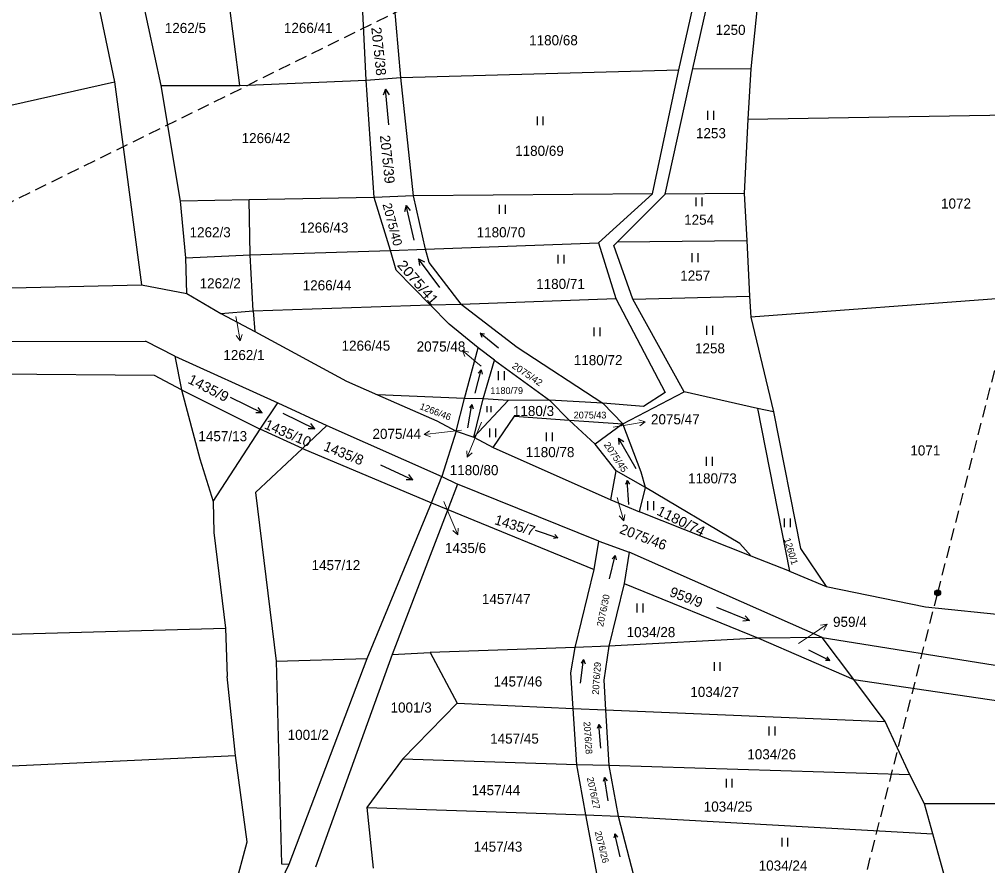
# Model space of a CAD drawing. Extents: x -820420 to -815896, y -1105820 to -1103643.
# Drawn here: x -818424.2 to -818260.8, y -1104579.4 to -1104436.5 of the extents above; entities that cross this region are included whole.
import ezdxf
from ezdxf.enums import TextEntityAlignment as Align

# ---------------------------------------------------------------- set-up
doc = ezdxf.new("R2010")
doc.units = 0
doc.header["$LTSCALE"] = 0.68
doc.linetypes.add('MEDIUM_DASHED', pattern=[4.5, 3, -1.5])
for name, color, linetype, lineweight in [('1', 7, 'Continuous', 25), ('3', 7, 'Continuous', 25), ('6', 7, 'Continuous', 25), ('7', 7, 'Continuous', 13)]:
    doc.layers.add(name, color=color, linetype=linetype, lineweight=lineweight)
doc.layers.add('2', color=7, linetype='Continuous')

msp = doc.modelspace()

# ---------------------------------------------------------------- linework, layer by layer
at = {"layer": '1'}
for p, q in [((-818419, -1104394.95), (-818408.15, -1104447.11)), ((-818400.28, -1104447.7), (-818404.63, -1104427.35)), ((-818386.97, -1104447.71), (-818389.54, -1104427.58)), ((-818359.79, -1104446.38), (-818361.33, -1104428.52)), ((-818312.89, -1104445.04), (-818309.55, -1104430.24)), ((-818310.49, -1104444.84), (-818307.33, -1104430.54)), ((-818299.29, -1104430.76), (-818300.71, -1104444.9)), ((-818359.79, -1104446.38), (-818312.89, -1104445.04)), ((-818317.32, -1104466.01), (-818312.89, -1104445.04)), ((-818315.17, -1104466.05), (-818310.49, -1104444.84)), ((-818310.49, -1104444.84), (-818300.71, -1104444.9)), ((-818300.71, -1104444.9), (-818301.21, -1104453.37)), ((-818451.46, -1104456.83), (-818408.15, -1104447.11)), ((-818408.15, -1104447.11), (-818403.58, -1104481.37)), ((-818386.97, -1104447.71), (-818365.63, -1104446.8)), ((-818365.63, -1104446.8), (-818359.79, -1104446.38)), ((-818364.31, -1104466.64), (-818365.63, -1104446.8)), ((-818357.69, -1104466.34), (-818359.79, -1104446.38)), ((-818396.98, -1104467.21), (-818400.28, -1104447.7)), ((-818400.28, -1104447.7), (-818386.97, -1104447.71)), ((-818301.21, -1104453.37), (-818226.13, -1104452.14)), ((-818301.21, -1104453.37), (-818301.84, -1104465.94)), ((-818385.42, -1104466.98), (-818396.98, -1104467.21)), ((-818364.31, -1104466.64), (-818385.42, -1104466.98)), ((-818385.26, -1104476.32), (-818385.42, -1104466.98)), ((-818357.69, -1104466.34), (-818364.31, -1104466.64)), ((-818361.57, -1104475.54), (-818364.31, -1104466.64)), ((-818317.32, -1104466.01), (-818357.69, -1104466.34)), ((-818355.64, -1104475.33), (-818357.69, -1104466.34)), ((-818326.41, -1104474.27), (-818317.32, -1104466.01)), ((-818323.25, -1104474.12), (-818315.17, -1104466.05)), ((-818301.84, -1104465.94), (-818315.17, -1104466.05)), ((-818301.84, -1104465.94), (-818301.42, -1104473.9)), ((-818396.12, -1104476.78), (-818396.98, -1104467.21)), ((-818355.64, -1104475.33), (-818326.41, -1104474.27)), ((-818326.41, -1104474.27), (-818323.5, -1104483.66)), ((-818323.83, -1104474.71), (-818323.25, -1104474.12)), ((-818320.65, -1104483.76), (-818323.83, -1104474.71)), ((-818323.25, -1104474.12), (-818301.42, -1104473.9)), ((-818301.42, -1104473.9), (-818300.93, -1104483.27)), ((-818396.12, -1104476.78), (-818385.26, -1104476.32)), ((-818395.9, -1104482.8), (-818396.12, -1104476.78)), ((-818385.26, -1104476.32), (-818361.57, -1104475.54)), ((-818384.71, -1104485.74), (-818385.26, -1104476.32)), ((-818361.57, -1104475.54), (-818355.64, -1104475.33)), ((-818360.6, -1104478.86), (-818361.57, -1104475.54)), ((-818355.04, -1104477.57), (-818355.64, -1104475.33)), ((-818349.6, -1104484.6), (-818355.04, -1104477.57)), ((-818354.87, -1104484.72), (-818360.6, -1104478.86)), ((-818513.64, -1104483.89), (-818403.58, -1104481.37)), ((-818403.58, -1104481.37), (-818395.9, -1104482.8)), ((-818395.9, -1104482.8), (-818390.18, -1104486.22)), ((-818320.65, -1104483.76), (-818300.93, -1104483.27)), ((-818300.93, -1104483.27), (-818300.75, -1104486.83)), ((-818250.48, -1104483.05), (-818300.75, -1104486.83)), ((-818384.71, -1104485.74), (-818354.87, -1104484.72)), ((-818354.87, -1104484.72), (-818349.6, -1104484.6)), ((-818351.62, -1104488.01), (-818354.87, -1104484.72)), ((-818349.6, -1104484.6), (-818323.5, -1104483.66)), ((-818349.6, -1104484.6), (-818340.14, -1104491.86)), ((-818323.5, -1104483.66), (-818315.18, -1104499.54)), ((-818311.99, -1104499.41), (-818320.65, -1104483.76)), ((-818390.18, -1104486.22), (-818384.71, -1104485.74)), ((-818390.18, -1104486.22), (-818384.47, -1104489.23)), ((-818384.71, -1104485.74), (-818384.47, -1104489.23)), ((-818346.76, -1104491.98), (-818351.62, -1104488.01)), ((-818300.75, -1104486.83), (-818296.92, -1104502.82)), ((-818384.47, -1104489.23), (-818368.98, -1104497.61)), ((-818428.81, -1104490.91), (-818402.92, -1104490.85)), ((-818397.95, -1104493.39), (-818402.92, -1104490.85)), ((-818349.08, -1104500.56), (-818346.76, -1104491.98)), ((-818343.99, -1104494.06), (-818346.76, -1104491.98)), ((-818340.14, -1104491.86), (-818325.7, -1104501.31)), ((-818397.95, -1104493.39), (-818396.82, -1104499.07)), ((-818397.95, -1104493.39), (-818380.57, -1104501.26)), ((-818345.91, -1104500.62), (-818343.99, -1104494.06)), ((-818343.99, -1104494.06), (-818334.7, -1104500.84)), ((-818401.41, -1104496.65), (-818518.56, -1104495.77)), ((-818396.82, -1104499.07), (-818401.41, -1104496.65)), ((-818368.98, -1104497.61), (-818363.75, -1104499.92)), ((-818396.82, -1104499.07), (-818383.56, -1104505.7)), ((-818396.82, -1104499.07), (-818393.74, -1104510.75)), ((-818322.31, -1104504.84), (-818311.99, -1104499.41)), ((-818315.18, -1104499.54), (-818318.86, -1104501.87)), ((-818299.59, -1104502.21), (-818311.99, -1104499.41)), ((-818383.56, -1104505.7), (-818380.57, -1104501.26)), ((-818380.57, -1104501.26), (-818372.32, -1104505.09)), ((-818363.75, -1104499.92), (-818353.72, -1104504.34)), ((-818350.45, -1104506.05), (-818349.08, -1104500.56)), ((-818347.5, -1104507.08), (-818345.91, -1104500.62)), ((-818341.67, -1104500.87), (-818347.5, -1104507.08)), ((-818341.67, -1104500.87), (-818345.91, -1104500.62)), ((-818334.7, -1104500.84), (-818341.67, -1104500.87)), ((-818325.7, -1104501.31), (-818334.7, -1104500.84)), ((-818334.7, -1104500.84), (-818331.4, -1104504.2)), ((-818322.31, -1104504.84), (-818325.7, -1104501.31)), ((-818318.86, -1104501.87), (-818325.7, -1104501.31)), ((-818299.59, -1104502.21), (-818294.22, -1104529.71)), ((-818296.92, -1104502.82), (-818299.59, -1104502.21)), ((-818296.92, -1104502.82), (-818292.32, -1104525.87)), ((-818353.72, -1104504.34), (-818350.45, -1104506.05)), ((-818344.21, -1104508.8), (-818340.61, -1104503.54)), ((-818340.61, -1104503.54), (-818331.4, -1104504.2)), ((-818331.4, -1104504.2), (-818327, -1104508.25)), ((-818331.4, -1104504.2), (-818322.31, -1104504.84)), ((-818391.49, -1104517.94), (-818383.56, -1104505.7)), ((-818376.38, -1104509.01), (-818383.56, -1104505.7)), ((-818372.32, -1104505.09), (-818376.38, -1104509.01)), ((-818372.32, -1104505.09), (-818352.91, -1104513.7)), ((-818350.45, -1104506.05), (-818352.91, -1104513.7)), ((-818350.45, -1104506.05), (-818347.5, -1104507.08)), ((-818322.31, -1104504.84), (-818327, -1104508.25)), ((-818319.22, -1104512.98), (-818322.31, -1104504.84)), ((-818347.5, -1104507.08), (-818344.21, -1104508.8)), ((-818376.38, -1104509.01), (-818384.31, -1104516.44)), ((-818376.38, -1104509.01), (-818354.64, -1104518.15)), ((-818344.21, -1104508.8), (-818324.37, -1104517.66)), ((-818323.48, -1104512.75), (-818327, -1104508.25)), ((-818393.74, -1104510.75), (-818391.49, -1104517.94)), ((-818324.37, -1104517.66), (-818323.48, -1104512.75)), ((-818318.48, -1104515.55), (-818323.48, -1104512.75)), ((-818354.64, -1104518.15), (-818352.91, -1104513.7)), ((-818352.91, -1104513.7), (-818350.22, -1104514.98)), ((-818318.48, -1104515.55), (-818319.22, -1104512.98)), ((-818350.22, -1104514.98), (-818351.89, -1104519.31)), ((-818326.39, -1104524.63), (-818350.22, -1104514.98)), ((-818319.51, -1104519.7), (-818318.48, -1104515.55)), ((-818302.6, -1104525), (-818318.48, -1104515.55)), ((-818384.31, -1104516.44), (-818380.84, -1104544.89)), ((-818324.37, -1104517.66), (-818319.51, -1104519.7)), ((-818391.49, -1104517.94), (-818391.39, -1104523.17)), ((-818365.48, -1104544.43), (-818354.64, -1104518.15)), ((-818351.89, -1104519.31), (-818361.28, -1104543.79)), ((-818354.64, -1104518.15), (-818351.89, -1104519.31)), ((-818351.89, -1104519.31), (-818327.16, -1104529.42)), ((-818300.68, -1104527.15), (-818319.51, -1104519.7)), ((-818391.39, -1104523.17), (-818389.39, -1104539.29)), ((-818327.16, -1104529.42), (-818326.39, -1104524.63)), ((-818326.39, -1104524.63), (-818321.26, -1104526.51)), ((-818302.6, -1104525), (-818300.68, -1104527.15)), ((-818321.26, -1104526.51), (-818322.13, -1104531.79)), ((-818288.7, -1104540.87), (-818321.26, -1104526.51)), ((-818294.22, -1104529.71), (-818300.68, -1104527.15)), ((-818292.32, -1104525.87), (-818288, -1104532.29)), ((-818330.35, -1104542.58), (-818327.16, -1104529.42)), ((-818294.22, -1104529.71), (-818288, -1104532.29)), ((-818322.13, -1104531.79), (-818324.7, -1104542.33)), ((-818322.13, -1104531.79), (-818299.45, -1104541)), ((-818288, -1104532.29), (-818271.24, -1104535.73)), ((-818271.24, -1104535.73), (-818252.18, -1104537.64)), ((-818465.14, -1104541.42), (-818389.39, -1104539.29)), ((-818389.39, -1104539.29), (-818389.11, -1104547.47)), ((-818299.45, -1104541), (-818324.7, -1104542.33)), ((-818288.7, -1104540.87), (-818299.45, -1104541)), ((-818299.45, -1104541), (-818283.33, -1104547.98)), ((-818288.7, -1104540.87), (-818248.29, -1104547.36)), ((-818283.33, -1104547.98), (-818288.7, -1104540.87)), ((-818361.28, -1104543.79), (-818374.22, -1104579.64)), ((-818361.28, -1104543.79), (-818354.85, -1104543.45)), ((-818330.35, -1104542.58), (-818354.85, -1104543.45)), ((-818354.85, -1104543.45), (-818350.28, -1104551.98)), ((-818331.12, -1104546.83), (-818330.35, -1104542.58)), ((-818324.7, -1104542.33), (-818330.35, -1104542.58)), ((-818324.7, -1104542.33), (-818325.56, -1104548.11)), ((-818380.84, -1104544.89), (-818365.48, -1104544.43)), ((-818380.84, -1104544.89), (-818379.96, -1104579.08)), ((-818378.66, -1104579.17), (-818365.48, -1104544.43)), ((-818330.72, -1104552.87), (-818331.12, -1104546.83)), ((-818387.71, -1104560.84), (-818389.11, -1104547.47)), ((-818325.56, -1104548.11), (-818325.26, -1104553.1)), ((-818283.33, -1104547.98), (-818211.91, -1104558.58)), ((-818278.05, -1104555.07), (-818283.33, -1104547.98)), ((-818350.28, -1104551.98), (-818359.51, -1104561.45)), ((-818350.28, -1104551.98), (-818330.72, -1104552.87)), ((-818330.72, -1104552.87), (-818325.26, -1104553.1)), ((-818330.09, -1104562.4), (-818330.72, -1104552.87)), ((-818325.26, -1104553.1), (-818278.05, -1104555.07)), ((-818325.26, -1104553.1), (-818324.7, -1104562.48)), ((-818273.9, -1104564.1), (-818278.05, -1104555.07)), ((-818489.62, -1104565.43), (-818387.71, -1104560.84)), ((-818385.75, -1104575.41), (-818387.71, -1104560.84)), ((-818359.51, -1104561.45), (-818365.54, -1104569.6)), ((-818330.09, -1104562.4), (-818359.51, -1104561.45)), ((-818328.55, -1104570.82), (-818330.09, -1104562.4)), ((-818324.7, -1104562.48), (-818330.09, -1104562.4)), ((-818273.9, -1104564.1), (-818324.7, -1104562.48)), ((-818324.7, -1104562.48), (-818323.1, -1104571.04)), ((-818271.4, -1104568.99), (-818273.9, -1104564.1)), ((-818365.54, -1104569.6), (-818364.46, -1104579.82)), ((-818365.54, -1104569.6), (-818328.55, -1104570.82)), ((-818177.63, -1104569.05), (-818271.4, -1104568.99)), ((-818269.99, -1104574.05), (-818271.4, -1104568.99)), ((-818326.67, -1104581), (-818328.55, -1104570.82)), ((-818328.55, -1104570.82), (-818323.1, -1104571.04)), ((-818323.1, -1104571.04), (-818320.52, -1104581)), ((-818323.1, -1104571.04), (-818269.99, -1104574.05)), ((-818267.52, -1104583.01), (-818269.99, -1104574.05)), ((-818391.09, -1104595.37), (-818385.75, -1104575.41)), ((-818385.92, -1104594.27), (-818378.66, -1104579.17)), ((-818379.96, -1104579.08), (-818378.66, -1104579.17))]:
    msp.add_line(p, q, dxfattribs=at)
for points in [[(-818365.63, -1104446.8), (-818366.53, -1104428.31), (-818367.08, -1104418.7)], [(-818345.91, -1104500.62), (-818349.08, -1104500.56), (-818363.75, -1104499.92)]]:
    msp.add_lwpolyline(points, dxfattribs=at)
at = {"layer": '3'}
for p, q in [((-818362.374, -1104448.344), (-818361.79, -1104449.273)), ((-818307.971, -1104453.48), (-818307.971, -1104451.98)), ((-818306.97, -1104453.48), (-818306.97, -1104451.98)), ((-818336.761, -1104454.43), (-818336.761, -1104452.93)), ((-818335.76, -1104454.43), (-818335.76, -1104452.93)), ((-818309.961, -1104468.09), (-818309.961, -1104466.59)), ((-818308.96, -1104468.09), (-818308.96, -1104466.59)), ((-818358.91, -1104467.978), (-818358.202, -1104468.818)), ((-818343.121, -1104469.36), (-818343.121, -1104467.86)), ((-818342.12, -1104469.36), (-818342.12, -1104467.86)), ((-818333.221, -1104477.78), (-818333.221, -1104476.28)), ((-818332.22, -1104477.78), (-818332.22, -1104476.28)), ((-818310.621, -1104477.52), (-818310.621, -1104476.02)), ((-818309.62, -1104477.52), (-818309.62, -1104476.02)), ((-818356.819, -1104476.995), (-818355.83, -1104477.474)), ((-818346.417, -1104489.503), (-818345.697, -1104489.654)), ((-818327.161, -1104490.05), (-818327.161, -1104488.55)), ((-818326.16, -1104490.05), (-818326.16, -1104488.55)), ((-818308.131, -1104489.8), (-818308.131, -1104488.3)), ((-818307.13, -1104489.8), (-818307.13, -1104488.3)), ((-818346.265, -1104495.73), (-818346.098, -1104496.446)), ((-818343.331, -1104497.44), (-818343.331, -1104495.94)), ((-818342.33, -1104497.44), (-818342.33, -1104495.94)), ((-818383.202, -1104502.97), (-818384.3, -1104502.993)), ((-818347.793, -1104501.56), (-818347.576, -1104502.263)), ((-818345.232, -1104502.87), (-818345.232, -1104501.865)), ((-818344.562, -1104502.87), (-818344.562, -1104501.865)), ((-818374.342, -1104505.66), (-818375.44, -1104505.683)), ((-818344.761, -1104507.09), (-818344.761, -1104505.59)), ((-818343.76, -1104507.09), (-818343.76, -1104505.59)), ((-818335.221, -1104507.76), (-818335.221, -1104506.26)), ((-818334.22, -1104507.76), (-818334.22, -1104506.26)), ((-818323.061, -1104507.233), (-818322.138, -1104507.828)), ((-818308.221, -1104511.92), (-818308.221, -1104510.42)), ((-818307.22, -1104511.92), (-818307.22, -1104510.42)), ((-818357.779, -1104514.263), (-818358.877, -1104514.304)), ((-818321.605, -1104514.403), (-818321.224, -1104515.033)), ((-818318.121, -1104519.39), (-818318.121, -1104517.89)), ((-818317.12, -1104519.39), (-818317.12, -1104517.89)), ((-818295.051, -1104522.28), (-818295.051, -1104520.78)), ((-818294.05, -1104522.28), (-818294.05, -1104520.78)), ((-818333.299, -1104524.04), (-818334.026, -1104524.157)), ((-818323.625, -1104527.06), (-818323.458, -1104527.776)), ((-818319.901, -1104536.67), (-818319.901, -1104535.17)), ((-818318.9, -1104536.67), (-818318.9, -1104535.17)), ((-818300.976, -1104538.038), (-818302.07, -1104538.137)), ((-818328.968, -1104544.634), (-818328.714, -1104545.325)), ((-818306.881, -1104546.54), (-818306.881, -1104545.04)), ((-818305.88, -1104546.54), (-818305.88, -1104545.04)), ((-818287.396, -1104544.751), (-818288.131, -1104544.766)), ((-818326.38, -1104555.576), (-818325.989, -1104556.199)), ((-818297.611, -1104557.41), (-818297.611, -1104555.91)), ((-818296.61, -1104557.41), (-818296.61, -1104555.91)), ((-818325.411, -1104564.523), (-818324.976, -1104565.117)), ((-818304.851, -1104566.24), (-818304.851, -1104564.74)), ((-818303.85, -1104566.24), (-818303.85, -1104564.74)), ((-818323.679, -1104574.019), (-818323.205, -1104574.581)), ((-818295.461, -1104576.2), (-818295.461, -1104574.7)), ((-818294.46, -1104576.2), (-818294.46, -1104574.7))]:
    msp.add_line(p, q, dxfattribs=at)
for points in [[(-818361.851, -1104454.321), (-818362.374, -1104448.344), (-818362.789, -1104449.361)], [(-818357.561, -1104473.824), (-818358.91, -1104467.978), (-818359.179, -1104469.043)], [(-818353.208, -1104481.787), (-818356.819, -1104476.995), (-818356.631, -1104478.077)], [(-818343.293, -1104492.033), (-818346.417, -1104489.503), (-818346.12, -1104490.176)], [(-818347.238, -1104499.631), (-818346.265, -1104495.73), (-818346.75, -1104496.284)], [(-818388.595, -1104500.34), (-818383.202, -1104502.97), (-818383.86, -1104502.091)], [(-818348.491, -1104505.519), (-818347.793, -1104501.56), (-818348.238, -1104502.147)], [(-818379.735, -1104503.03), (-818374.342, -1104505.66), (-818375, -1104504.781)], [(-818320.061, -1104512.429), (-818323.061, -1104507.233), (-818323.007, -1104508.33)], [(-818363.217, -1104511.727), (-818357.779, -1104514.263), (-818358.453, -1104513.395)], [(-818321.325, -1104518.413), (-818321.605, -1104514.403), (-818321.895, -1104515.08)], [(-818337.122, -1104522.798), (-818333.299, -1104524.04), (-818333.818, -1104523.518)], [(-818324.598, -1104530.961), (-818323.625, -1104527.06), (-818324.11, -1104527.614)], [(-818306.539, -1104535.791), (-818300.976, -1104538.038), (-818301.694, -1104537.207)], [(-818291.009, -1104542.989), (-818287.396, -1104544.751), (-818287.837, -1104544.162)], [(-818329.458, -1104548.624), (-818328.968, -1104544.634), (-818329.381, -1104545.243)], [(-818326.03, -1104559.58), (-818326.38, -1104555.576), (-818326.658, -1104556.257)], [(-818324.782, -1104568.493), (-818325.411, -1104564.523), (-818325.64, -1104565.222)], [(-818322.775, -1104577.936), (-818323.679, -1104574.019), (-818323.859, -1104574.733)]]:
    msp.add_lwpolyline(points, dxfattribs=at)
at = {"layer": '6', "linetype": 'MEDIUM_DASHED'}
for p, q in [((-818329.14, -1104419.82), (-818425.57, -1104467.38)), ((-818292.37, -1104624.54), (-818269.18, -1104533.35))]:
    msp.add_line(p, q, dxfattribs=at)
msp.add_lwpolyline([(-818269.18, -1104533.35), (-818248.07, -1104451.05), (-818232.5, -1104368.04)], dxfattribs=at)
at = {"layer": '6'}
for radius in [0.5, 0.4, 0.3, 0.2, 0.1]:
    msp.add_circle((-818269.1834, -1104533.3499), radius, dxfattribs=at)
at = {"layer": '7'}
for p, q in [((-818386.909, -1104490.815), (-818386.59, -1104489.742)), ((-818349.419, -1104492.441), (-818348.974, -1104493.468)), ((-818318.576, -1104504.501), (-818319.643, -1104504.163)), ((-818355.869, -1104506.626), (-818354.814, -1104507.001)), ((-818348.584, -1104510.472), (-818347.745, -1104509.732)), ((-818322.183, -1104521.205), (-818321.978, -1104520.104)), ((-818350.177, -1104523.572), (-818350.108, -1104522.455)), ((-818287.852, -1104538.662), (-818288.962, -1104538.807))]:
    msp.add_line(p, q, dxfattribs=at)
for points in [[(-818387.64, -1104486.69), (-818387.43, -1104487.86), (-818386.909, -1104490.815), (-818387.576, -1104489.916)], [(-818346.26, -1104495.1), (-818347.12, -1104494.37), (-818349.419, -1104492.441), (-818348.33, -1104492.701)], [(-818346.2, -1104504.55), (-818347.46, -1104507.69), (-818348.584, -1104510.472), (-818348.673, -1104509.356)], [(-818323.95, -1104505.37), (-818321.54, -1104504.97), (-818318.576, -1104504.501), (-818319.487, -1104505.152)], [(-818349.57, -1104505.87), (-818352.89, -1104506.26), (-818355.869, -1104506.626), (-818354.936, -1104506.007)], [(-818323.31, -1104517.26), (-818323.01, -1104518.32), (-818322.183, -1104521.205), (-818322.94, -1104520.38)], [(-818352.55, -1104517.95), (-818351.35, -1104520.81), (-818350.177, -1104523.572), (-818351.03, -1104522.846)], [(-818292.65, -1104541.89), (-818290.34, -1104540.34), (-818287.852, -1104538.662), (-818288.402, -1104539.637)]]:
    msp.add_lwpolyline(points, dxfattribs=at)

# ---------------------------------------------------------------- texts
at = {"layer": '2'}
for s, height, p in [('1262/5', 1.7, (-818396.17, -1104438.845)), ('1266/41', 1.7, (-818375.429, -1104438.835)), ('1250', 1.7, (-818304.14, -1104439.165)), ('1180/68', 1.7, (-818334.039, -1104440.915)), ('1253', 1.7, (-818307.46, -1104456.605)), ('1266/42', 1.7, (-818382.569, -1104457.435)), ('1180/69', 1.7, (-818336.399, -1104459.585)), ('1072', 1.7, (-818266.09, -1104468.485)), ('1254', 1.7, (-818309.45, -1104471.215)), ('1262/3', 1.7, (-818391.99, -1104473.335)), ('1266/43', 1.7, (-818372.759, -1104472.545)), ('1180/70', 1.7, (-818342.899, -1104473.335)), ('1257', 1.7, (-818310.11, -1104480.645)), ('1262/2', 1.7, (-818390.29, -1104481.955)), ('1266/44', 1.7, (-818372.259, -1104482.285)), ('1180/71', 1.7, (-818332.849, -1104482.055)), ('1266/45', 1.7, (-818365.699, -1104492.475)), ('1258', 1.7, (-818307.62, -1104492.925)), ('1180/72', 1.7, (-818326.499, -1104494.915)), ('1180/79', 1.14, (-818341.93, -1104499.785)), ('1180/3', 1.7, (-818337.41, -1104503.505)), ('2075/43', 1.14, (-818327.87, -1104503.915)), ('1457/13', 1.7, (-818389.859, -1104507.755)), ('1180/78', 1.7, (-818334.609, -1104510.445)), ('1071', 1.7, (-818271.27, -1104510.165)), ('1180/73', 1.7, (-818307.209, -1104514.875)), ('1457/12', 1.7, (-818370.759, -1104529.525)), ('1457/47', 1.7, (-818342.009, -1104535.235)), ('1034/28', 1.7, (-818317.579, -1104540.835)), ('1457/46', 1.7, (-818340.039, -1104549.165)), ('1034/27', 1.7, (-818306.829, -1104550.925)), ('1001/3', 1.7, (-818358.06, -1104553.565)), ('1001/2', 1.7, (-818375.43, -1104558.175)), ('1457/45', 1.7, (-818340.619, -1104558.805)), ('1034/26', 1.7, (-818297.209, -1104561.455)), ('1457/44', 1.7, (-818343.749, -1104567.515)), ('1034/25', 1.7, (-818304.559, -1104570.285)), ('1457/43', 1.7, (-818343.399, -1104577.055)), ('1034/24', 1.7, (-818295.289, -1104580.245))]:
    msp.add_text(s, height=height, dxfattribs=at).set_placement(p, align=Align.CENTER)
for s, height, rotation, p in [('2075/38', 1.7, 276, (-818364.367, -1104442.0297)), ('2075/39', 1.7, 276, (-818362.917, -1104460.2597)), ('2075/40', 1.53, 285, (-818361.9518, -1104471.349)), ('1266/46', 1.14, 339, (-818354.1473, -1104503.2954)), ('1435/10', 1.7, 337, (-818379.1971, -1104507.1724)), ('1435/8', 1.7, 338, (-818369.7569, -1104510.559)), ('1435/7', 1.7, 343, (-818340.7875, -1104522.7542)), ('1260/1', 1.14, 287, (-818294.4864, -1104526.5078)), ('959/9', 1.7, 339, (-818311.9271, -1104534.8859)), ('2076/30', 1.139, 78, (-818325.0885, -1104536.4489)), ('2076/29', 1.139, 86, (-818326.1941, -1104547.8187)), ('2076/28', 1.14, 274, (-818328.772, -1104557.8697)), ('2076/27', 1.14, 282, (-818327.835, -1104567.2895)), ('2076/26', 1.139, 284, (-818326.4185, -1104576.3982))]:
    msp.add_text(s, height=height, rotation=rotation, dxfattribs=at).set_placement(p, align=Align.CENTER)
for s, height, rotation, width, p in [('2075/41', 1.7, 311, 1.1, (-818357.5534, -1104481.5019)), ('2075/42', 1.139, 326, 1.05, (-818338.7565, -1104496.9151)), ('1435/9', 1.7, 333, 1.05, (-818392.6559, -1104499.5278)), ('2075/45', 1.14, 304, 1.05, (-818323.9764, -1104510.7608)), ('1180/74', 1.7, 334, 1.05, (-818312.8766, -1104521.9942))]:
    msp.add_text(s, height=height, rotation=rotation, dxfattribs=dict(at, width=width)).set_placement(p, align=Align.CENTER)
for s, p in [('2075/48', (-818348.91, -1104492.615)), ('2075/44', (-818356.37, -1104507.365)), ('1180/80', (-818343.33, -1104513.485))]:
    msp.add_text(s, height=1.7, dxfattribs=at).set_placement(p, align=Align.RIGHT)
for s, p in [('1262/1', (-818389.76, -1104494.055)), ('2075/47', (-818317.58, -1104504.905)), ('1435/6', (-818352.36, -1104526.635)), ('959/4', (-818286.85, -1104539.095))]:
    msp.add_text(s, height=1.7, dxfattribs=at).set_placement(p)
msp.add_text('2075/46', height=1.7, rotation=339, dxfattribs=at).set_placement((-818323.009, -1104523.245))

doc.saveas('drawing.dxf')
